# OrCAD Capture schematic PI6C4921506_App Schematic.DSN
size B; title: PI6C4921506 Application Circuit; rev: 1.0; note: Diodes Inc. Clock IC Application Engineering
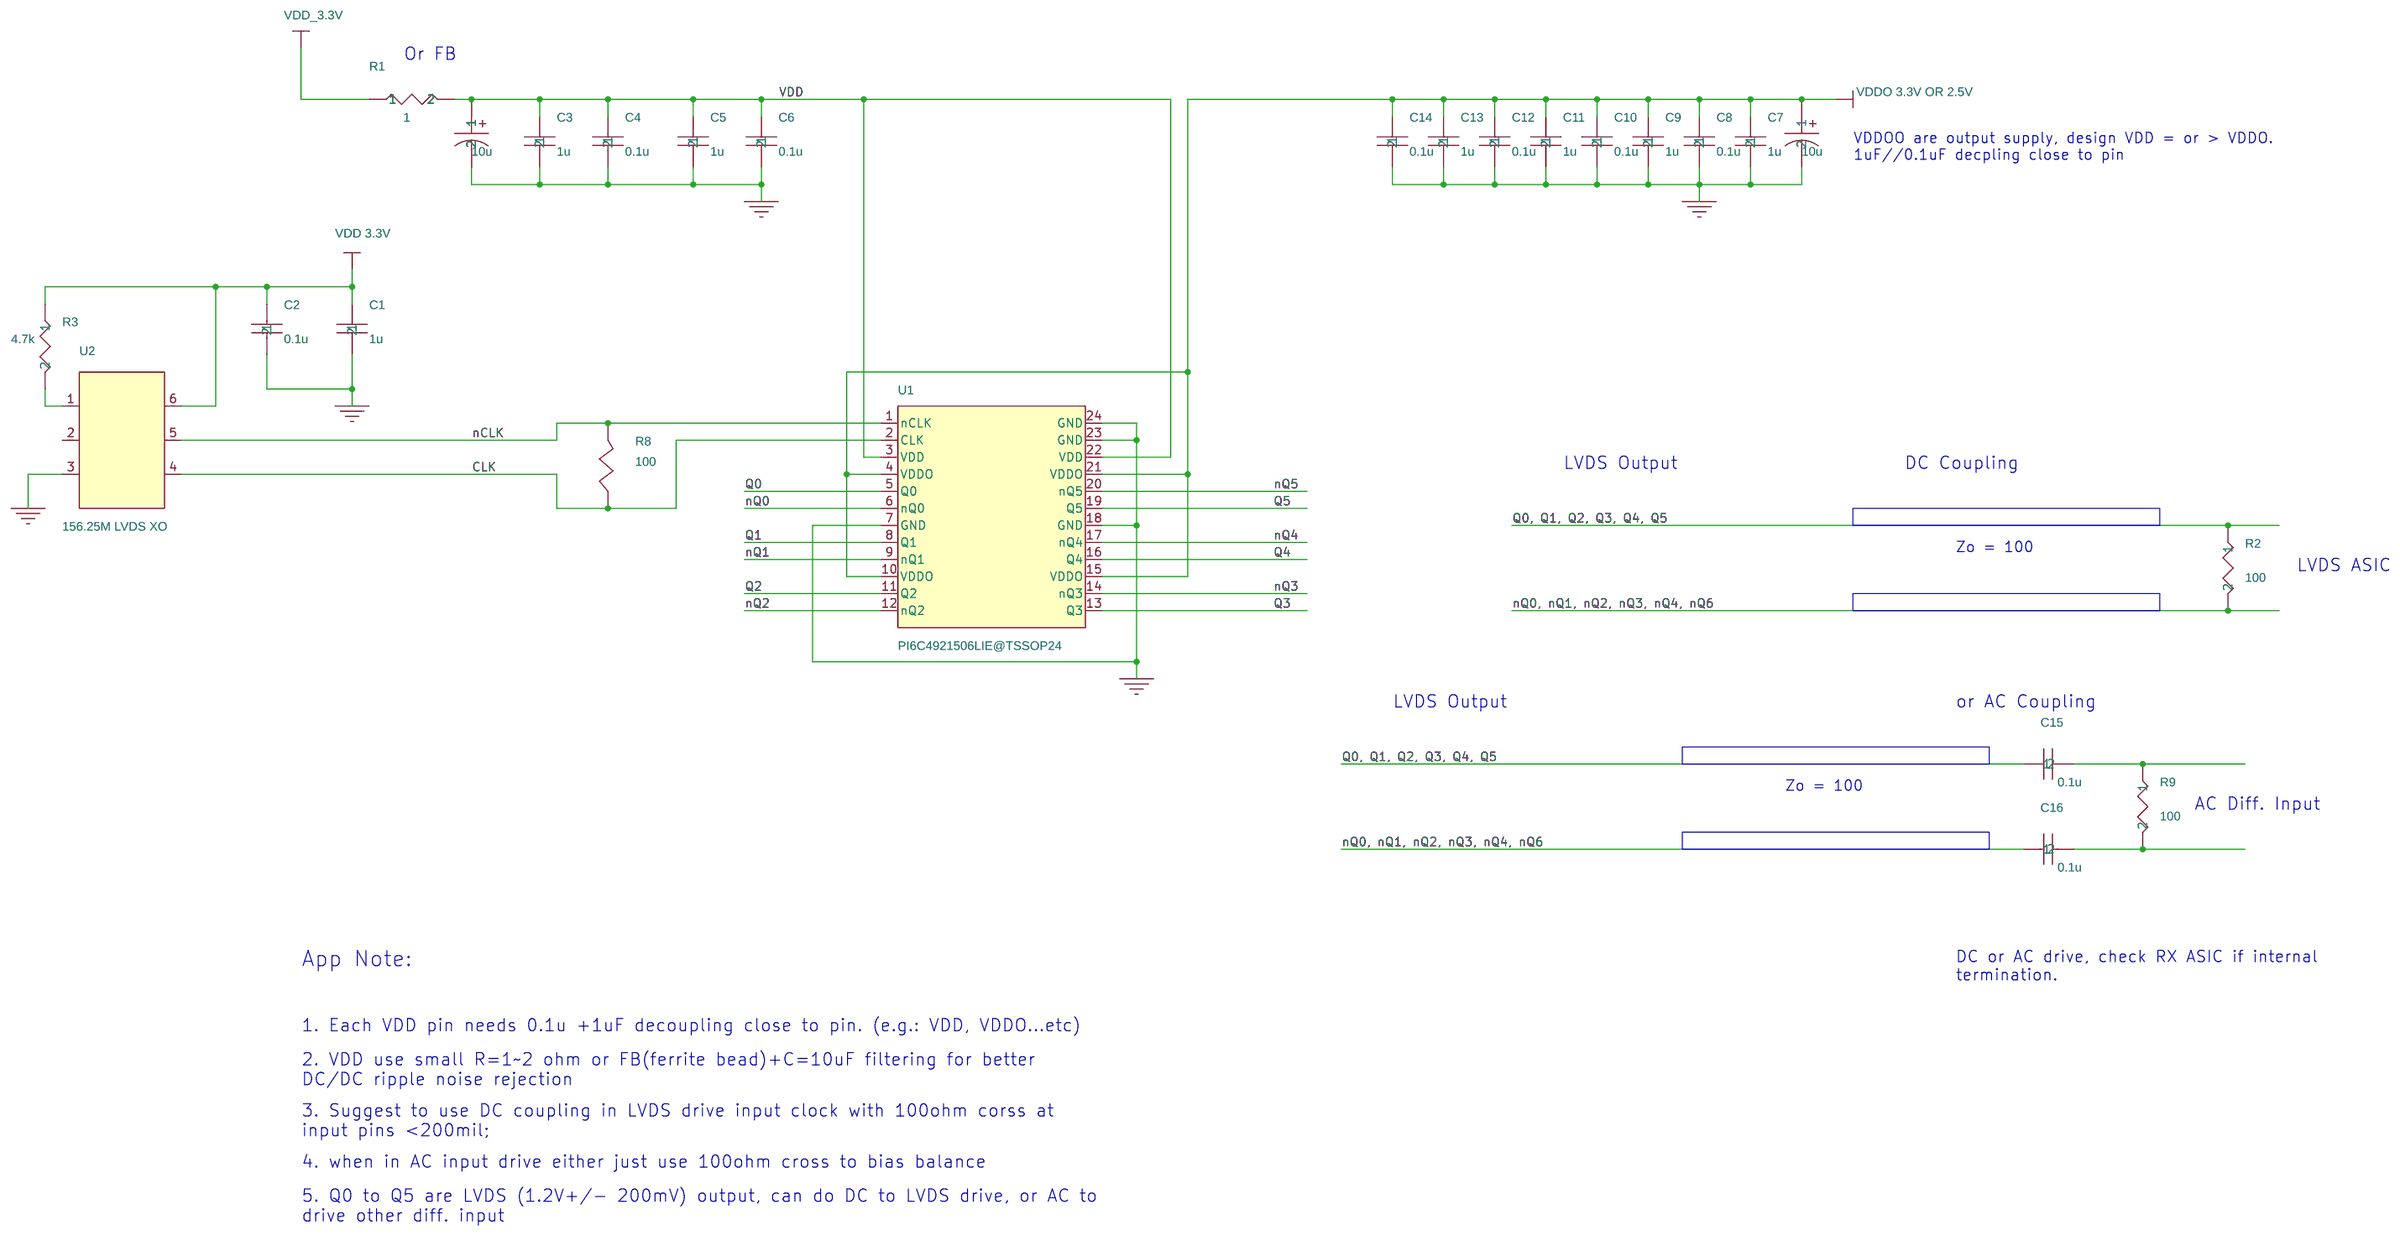
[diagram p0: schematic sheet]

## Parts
C1  1u  [CC_0402]
C2  0.1u  [CC_0402]
C3  1u  [CC_0402]
C4  0.1u  [CC_0402]
C5  1u  [CC_0402]
C6  0.1u  [CC_0402]
C7  1u  [CC_0402]
C8  0.1u  [CC_0402]
C9  1u  [CC_0402]
C10  0.1u  [CC_0402]
C11  1u  [CC_0402]
C12  0.1u  [CC_0402]
C13  1u  [CC_0402]
C14  0.1u  [CC_0402]
C15  0.1u  [CC_0402]
C16  0.1u  [CC_0402]
EC1  10u  [CAP1000UF]
EC2  10u  [CAP1000UF]
R1  1  [R_0402]
R2  100  [R_0402]
R3  4.7k  [R_0402]
R8  100
R9  100  [R_0402]
U1  PI6C4921506LIE@TSSOP24  [TSSOP24]
U2  156.25M LVDS XO  [XO 5X7]

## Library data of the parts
C1 = C_0.1u_0402_8
C2 = C_0.1u_0402_7
C3 = C_0.1u_0402_10
C4 = C_0.1u_0402_1
C5 = C_0.1u_0402_6
C6 = C_0.1u_0402_3
C7 = C_0.1u_0402_15
C8 = C_0.1u_0402_9
C9 = C_0.1u_0402_5
C10 = C_0.1u_0402_4
C11 = C_0.1u_0402_12
C12 = C_0.1u_0402_11
C13 = C_0.1u_0402_14
C14 = C_0.1u_0402_13
C15 = C_0.1u_0402
C16 = C_0.1u_0402_2
EC1 = C_alum_1000u
EC2 = C_alum_1000u_1
R1 = R_0402_2
R2 = R_0402
R3 = R_0402_3
R8 = res1
R9 = R_0402_1
U1 = PI6C4911506LIE@TSSOP20_0
U2 = XO_5X7

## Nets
GND: C1.2 C2.2 C3.2 C4.2 C5.2 C6.2 C7.2 C8.2 C9.2 C10.2 C11.2 C12.2 C13.2 C14.2 EC1.2 EC2.2 U1.7(GND) U1.18(GND) U1.23(GND) U1.24(GND) U2.3
VDD: C3.1 C4.1 C5.1 C6.1 EC1.1 R1.2 U1.3(VDD) U1.22(VDD)
VDD 3.3V: C1.1 C2.1 R3.1 U2.6
VDD_3.3V: R1.1
VDDO 3.3V or 2.5V: C7.1 C8.1 C9.1 C10.1 C11.1 C12.1 C13.1 C14.1 EC2.1 U1.4(VDDO) U1.10(VDDO) U1.15(VDDO) U1.21(VDDO)
CLK: R8.1 U1.2(CLK) U2.4
nCLK: R8.2 U1.1(nCLK) U2.5
nQ0: U1.6(nQ0)
nQ0, nQ1, nQ2, nQ3, nQ4, nQ6: C16.1 R2.2
nQ1: U1.9(nQ1)
nQ2: U1.12(nQ2)
nQ3: U1.14(nQ3)
nQ4: U1.17(nQ4)
nQ5: U1.20(nQ5)
Q0: U1.5(Q0)
Q0, Q1, Q2, Q3, Q4, Q5: C15.1 R2.1
Q1: U1.8(Q1)
Q2: U1.11(Q2)
Q3: U1.13(Q3)
Q4: U1.16(Q4)
Q5: U1.19(Q5)
N3691829: R3.2 U2.1
N3695659: C15.2 R9.1
N3695722: C16.2 R9.2

Not connected (* = marked no-connect by the designer): U2 2

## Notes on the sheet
- Or FB
- VDDOO are output supply, design VDD = or > VDDO.
  1uF//0.1uF decpling close to pin
- LVDS Output
- DC Coupling
- Zo = 100
- LVDS ASIC
- LVDS Output
- or AC Coupling
- Zo = 100
- AC Diff. Input
- App Note:
- DC or AC drive, check RX ASIC if internal
  termination.
- 1. Each VDD pin needs 0.1u +1uF decoupling close to pin. (e.g.: VDD, VDDO...etc)
- 2. VDD use small R=1~2 ohm or FB(ferrite bead)+C=10uF filtering for better
  DC/DC ripple noise rejection
- 3. Suggest to use DC coupling in LVDS drive input clock with 100ohm corss at
  input pins <200mil;
- 4. when in AC input drive either just use 100ohm cross to bias balance
- 5. Q0 to Q5 are LVDS (1.2V+/- 200mV) output, can do DC to LVDS drive, or AC to
  drive other diff. input
